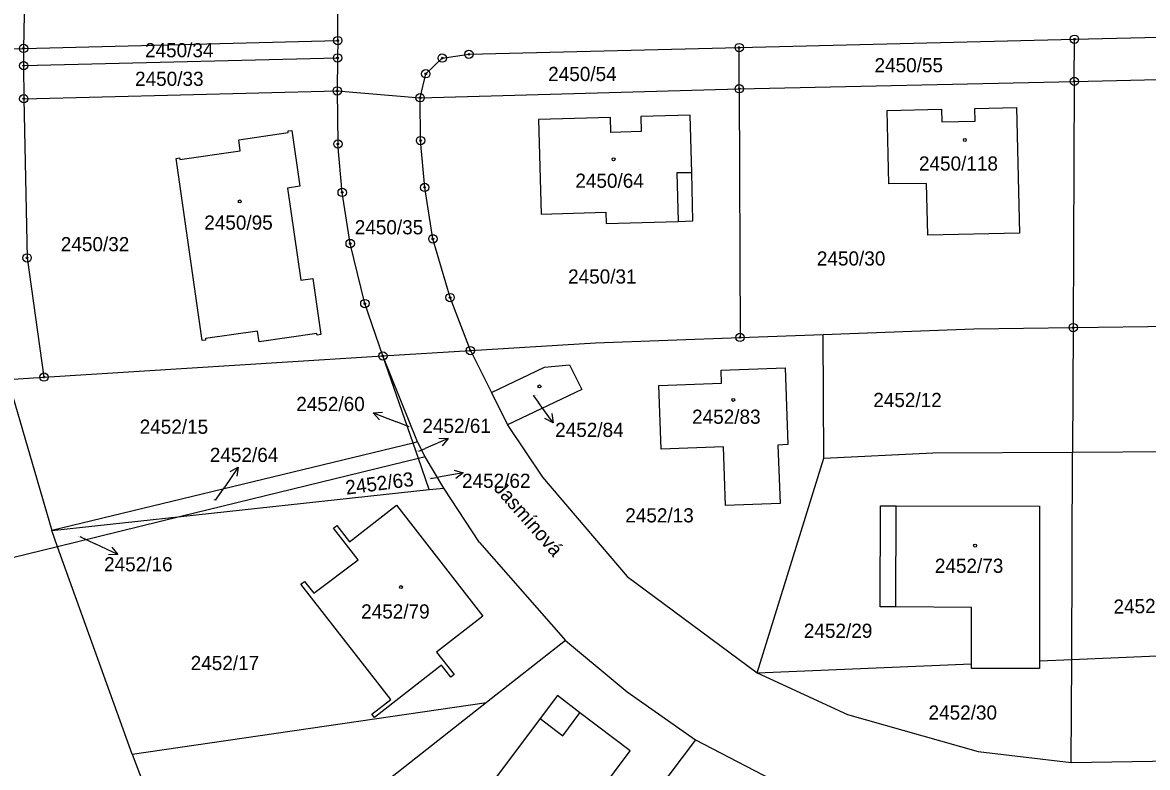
# Model space of a CAD drawing. Extents: x -755819 to -753140, y -1169796 to -1166000.
# Drawn here: x -755181.4 to -755046.4, y -1168484.4 to -1168395 of the extents above; entities that cross this region are included whole.
import ezdxf

# ---------------------------------------------------------------- set-up
doc = ezdxf.new("R2010")
doc.units = 0
for name, color, linetype in [('Vrstva 1', 7, 'Continuous'), ('Vrstva 15', 7, 'Continuous'), ('Vrstva 16', 7, 'Continuous'), ('Vrstva 18', 7, 'Continuous'), ('Vrstva 19', 7, 'Continuous'), ('Vrstva 24', 7, 'Continuous'), ('Vrstva 25', 7, 'Continuous'), ('Vrstva 4', 7, 'Continuous'), ('Vrstva 6', 7, 'Continuous')]:
    doc.layers.add(name, color=color, linetype=linetype)

msp = doc.modelspace()

# ---------------------------------------------------------------- linework, layer by layer
at = {"layer": 'Vrstva 1'}
for p, q in [((-755180.52, -1168361.47), (-755181.23, -1168398.1)), ((-755143.53, -1168397.15), (-755143.58, -1168361.49)), ((-755055.13, -1168396.99), (-755015.3, -1168396)), ((-755192.3, -1168398.38), (-755181.23, -1168398.1)), ((-755181.23, -1168398.1), (-755143.53, -1168397.15)), ((-755181.23, -1168398.1), (-755181.22, -1168400.16)), ((-755143.53, -1168397.15), (-755143.55, -1168399.23)), ((-755127.79, -1168398.8), (-755095.36, -1168397.99)), ((-755095.36, -1168397.99), (-755055.13, -1168396.99)), ((-755095.35, -1168402.94), (-755095.36, -1168397.99)), ((-755055.15, -1168402.05), (-755055.13, -1168396.99)), ((-755181.22, -1168400.16), (-755143.55, -1168399.23)), ((-755143.55, -1168399.23), (-755143.59, -1168403.19)), ((-755132.97, -1168401.14), (-755130.99, -1168399.26)), ((-755130.99, -1168399.26), (-755127.79, -1168398.8)), ((-755181.22, -1168400.16), (-755181.2, -1168404.13)), ((-755133.65, -1168404.02), (-755132.97, -1168401.14)), ((-755095.35, -1168402.94), (-755055.15, -1168402.05)), ((-755055.15, -1168402.05), (-755055.28, -1168431.59)), ((-755055.15, -1168402.05), (-755015.29, -1168401.09)), ((-755181.2, -1168404.13), (-755143.59, -1168403.19)), ((-755143.59, -1168403.19), (-755143.51, -1168409.56)), ((-755143.59, -1168403.19), (-755133.65, -1168404.02)), ((-755133.65, -1168404.02), (-755095.35, -1168402.94)), ((-755095.35, -1168402.94), (-755095.26, -1168432.77)), ((-755181.2, -1168404.13), (-755180.81, -1168423.22)), ((-755133.59, -1168409.15), (-755133.65, -1168404.02)), ((-755110.81, -1168406.39), (-755119.46, -1168406.62)), ((-755110.77, -1168408.19), (-755110.81, -1168406.39)), ((-755101.24, -1168406.12), (-755107.17, -1168406.28)), ((-755107.17, -1168406.28), (-755107.13, -1168408.06)), ((-755101.04, -1168413.02), (-755101.24, -1168406.12)), ((-755077.61, -1168405.55), (-755071.07, -1168405.4)), ((-755077.42, -1168414.34), (-755077.61, -1168405.55)), ((-755071.07, -1168405.4), (-755071.03, -1168406.9)), ((-755067.07, -1168405.31), (-755062.08, -1168405.2)), ((-755067.04, -1168406.81), (-755067.07, -1168405.31)), ((-755062.08, -1168405.2), (-755061.74, -1168420.24)), ((-755119.46, -1168406.62), (-755119.13, -1168417.97)), ((-755071.03, -1168406.9), (-755067.04, -1168406.81)), ((-755155.41, -1168409.07), (-755149.46, -1168408.18)), ((-755155.25, -1168410.38), (-755155.41, -1168409.07)), ((-755149.47, -1168407.99), (-755149.03, -1168407.96)), ((-755149.46, -1168408.18), (-755149.47, -1168407.99)), ((-755149.03, -1168407.96), (-755148.1, -1168414.63)), ((-755107.13, -1168408.06), (-755110.77, -1168408.19)), ((-755162.47, -1168411.44), (-755155.25, -1168410.38)), ((-755143, -1168415.37), (-755143.51, -1168409.56)), ((-755133.1, -1168414.78), (-755133.59, -1168409.15)), ((-755162.93, -1168411.29), (-755162.5, -1168411.24)), ((-755159.81, -1168433.15), (-755162.93, -1168411.29)), ((-755162.5, -1168411.24), (-755162.47, -1168411.44)), ((-755100.93, -1168418.78), (-755101.04, -1168413.02)), ((-755072.87, -1168414.29), (-755077.42, -1168414.34)), ((-755072.73, -1168420.48), (-755072.87, -1168414.29)), ((-755148.1, -1168414.63), (-755149.55, -1168414.85)), ((-755149.55, -1168414.85), (-755147.97, -1168425.9)), ((-755142.04, -1168421.5), (-755143, -1168415.37)), ((-755132.12, -1168420.94), (-755133.1, -1168414.78)), ((-755119.13, -1168417.97), (-755111.35, -1168417.74)), ((-755111.35, -1168417.74), (-755111.34, -1168419.09)), ((-755111.34, -1168419.09), (-755102.69, -1168418.85)), ((-755102.69, -1168418.85), (-755100.93, -1168418.78)), ((-755130.05, -1168427.99), (-755132.12, -1168420.94)), ((-755061.74, -1168420.24), (-755072.73, -1168420.48)), ((-755140.28, -1168428.71), (-755142.04, -1168421.5)), ((-755180.81, -1168423.22), (-755178.78, -1168437.53)), ((-755147.97, -1168425.9), (-755146.52, -1168425.71)), ((-755146.52, -1168425.71), (-755145.56, -1168432.42)), ((-755127.62, -1168434.34), (-755130.05, -1168427.99)), ((-755138.11, -1168434.99), (-755140.28, -1168428.71)), ((-755153.14, -1168432), (-755159.41, -1168432.88)), ((-755152.95, -1168433.29), (-755153.14, -1168432)), ((-755085.27, -1168432.41), (-755067.2, -1168431.75)), ((-755067.2, -1168431.75), (-755055.28, -1168431.59)), ((-755055.28, -1168431.59), (-755055.35, -1168446.53)), ((-755055.28, -1168431.59), (-755015.24, -1168431.05)), ((-755159.38, -1168433.08), (-755159.81, -1168433.15)), ((-755159.41, -1168432.88), (-755159.38, -1168433.08)), ((-755146.03, -1168432.29), (-755152.95, -1168433.29)), ((-755146, -1168432.48), (-755146.03, -1168432.29)), ((-755145.56, -1168432.42), (-755146, -1168432.48)), ((-755127.62, -1168434.34), (-755112.6, -1168433.4)), ((-755112.6, -1168433.4), (-755095.26, -1168432.77)), ((-755095.26, -1168432.77), (-755085.27, -1168432.41)), ((-755085.21, -1168447.26), (-755085.27, -1168432.41)), ((-755138.11, -1168434.99), (-755127.62, -1168434.34)), ((-755127.62, -1168434.34), (-755125.1, -1168439.38)), ((-755178.78, -1168437.53), (-755138.11, -1168434.99)), ((-755134.5, -1168445.44), (-755138.11, -1168434.99)), ((-755133.95, -1168445.3), (-755138.11, -1168434.99)), ((-755118.73, -1168436.35), (-755115.74, -1168436.05)), ((-755115.74, -1168436.05), (-755114.25, -1168439.03)), ((-755125.1, -1168439.38), (-755118.73, -1168436.35)), ((-755097.54, -1168436.7), (-755089.86, -1168436.41)), ((-755097.49, -1168438.26), (-755097.54, -1168436.7)), ((-755089.86, -1168436.41), (-755089.52, -1168445.62)), ((-755183.1, -1168437.8), (-755178.78, -1168437.53)), ((-755105.01, -1168438.52), (-755097.49, -1168438.26)), ((-755104.74, -1168446.18), (-755105.01, -1168438.52)), ((-755125.1, -1168439.38), (-755123.16, -1168443.26)), ((-755114.25, -1168439.03), (-755123.16, -1168443.26)), ((-755123.16, -1168443.26), (-755123.06, -1168443.45)), ((-755123.06, -1168443.45), (-755118.96, -1168449.54)), ((-755134.5, -1168445.44), (-755177.85, -1168455.95)), ((-755133.95, -1168445.3), (-755134.5, -1168445.44)), ((-755133.86, -1168447.3), (-755134.5, -1168445.44)), ((-755133.05, -1168447.1), (-755133.95, -1168445.3)), ((-755097.26, -1168445.89), (-755104.74, -1168446.18)), ((-755097.01, -1168452.92), (-755097.26, -1168445.89)), ((-755089.52, -1168445.62), (-755090.73, -1168445.7)), ((-755090.73, -1168445.7), (-755090.46, -1168452.71)), ((-755085.21, -1168447.26), (-755072.12, -1168446.63)), ((-755072.12, -1168446.63), (-755055.35, -1168446.53)), ((-755055.46, -1168471.41), (-755055.35, -1168446.53)), ((-755055.35, -1168446.53), (-755015.21, -1168446.3)), ((-755133.86, -1168447.3), (-755162.35, -1168454.27)), ((-755133.05, -1168447.1), (-755133.86, -1168447.3)), ((-755132.57, -1168451.03), (-755133.86, -1168447.3)), ((-755130.81, -1168450.84), (-755133.05, -1168447.1)), ((-755093.19, -1168472.99), (-755085.21, -1168447.26)), ((-755118.96, -1168449.54), (-755108.82, -1168461.44)), ((-755132.57, -1168451.03), (-755130.81, -1168450.84)), ((-755126.54, -1168457.36), (-755130.81, -1168450.84)), ((-755162.35, -1168454.27), (-755132.57, -1168451.03)), ((-755142.13, -1168457.28), (-755136.47, -1168452.9)), ((-755136.47, -1168452.9), (-755126.11, -1168466.19)), ((-755090.46, -1168452.71), (-755097.01, -1168452.92)), ((-755078.45, -1168465.09), (-755078.42, -1168452.96)), ((-755078.42, -1168452.96), (-755076.54, -1168452.97)), ((-755076.54, -1168452.97), (-755059.34, -1168453)), ((-755059.34, -1168453), (-755059.34, -1168471.57)), ((-755177.85, -1168455.95), (-755162.35, -1168454.27)), ((-755162.35, -1168454.27), (-755177.15, -1168457.89)), ((-755144.05, -1168455.65), (-755143.64, -1168455.35)), ((-755141.09, -1168459.43), (-755144.05, -1168455.65)), ((-755143.64, -1168455.35), (-755142.13, -1168457.28)), ((-755126.54, -1168457.36), (-755116.19, -1168469.11)), ((-755177.15, -1168457.89), (-755188.54, -1168460.68)), ((-755146.39, -1168463.44), (-755141.09, -1168459.43)), ((-755108.82, -1168461.44), (-755093.19, -1168472.99)), ((-755147.95, -1168462.35), (-755147.54, -1168462.05)), ((-755137.15, -1168476.19), (-755147.95, -1168462.35)), ((-755147.54, -1168462.05), (-755146.39, -1168463.44)), ((-755076.57, -1168465.1), (-755078.45, -1168465.09)), ((-755067.47, -1168465.15), (-755076.57, -1168465.1)), ((-755067.49, -1168471.91), (-755067.47, -1168465.15)), ((-755126.11, -1168466.19), (-755131.67, -1168470.51)), ((-755116.19, -1168469.11), (-755125.69, -1168476.58)), ((-755116.19, -1168469.11), (-755110.02, -1168474.29)), ((-755131.67, -1168470.51), (-755129.57, -1168473.21)), ((-755131.07, -1168472.09), (-755139.12, -1168478.36)), ((-755129.96, -1168473.52), (-755131.07, -1168472.09)), ((-755067.49, -1168472.47), (-755067.49, -1168471.91)), ((-755059.34, -1168472.49), (-755067.49, -1168472.47)), ((-755059.34, -1168471.57), (-755059.34, -1168472.49)), ((-755055.51, -1168483.78), (-755055.46, -1168471.41)), ((-755129.57, -1168473.21), (-755129.96, -1168473.52)), ((-755093.19, -1168472.99), (-755082.38, -1168478.02)), ((-755110.02, -1168474.29), (-755108.82, -1168475.29)), ((-755125.69, -1168476.58), (-755160.25, -1168503.73)), ((-755139.43, -1168477.97), (-755137.15, -1168476.19)), ((-755117.18, -1168475.73), (-755119.26, -1168478.5)), ((-755114.48, -1168477.8), (-755117.18, -1168475.73)), ((-755108.82, -1168475.29), (-755100.62, -1168481.04)), ((-755108.43, -1168482.37), (-755114.48, -1168477.8)), ((-755139.12, -1168478.36), (-755139.43, -1168477.97)), ((-755119.26, -1168478.5), (-755128.05, -1168490.22)), ((-755082.38, -1168478.02), (-755066.7, -1168482.46)), ((-755100.62, -1168481.04), (-755113.58, -1168498.25)), ((-755100.62, -1168481.04), (-755088.52, -1168487.31)), ((-755119.3, -1168496.79), (-755108.43, -1168482.37)), ((-755066.7, -1168482.46), (-755055.51, -1168483.78)), ((-755055.51, -1168483.78), (-755015.37, -1168483.03))]:
    msp.add_line(p, q, dxfattribs=at)
at = {"layer": 'Vrstva 16'}
for p, q in [((-755120.07, -1168439.72), (-755119.44, -1168440.58)), ((-755117.68, -1168443.01), (-755119.44, -1168440.58)), ((-755139.28, -1168441.83), (-755136.48, -1168442.9)), ((-755134.95, -1168443.48), (-755136.48, -1168442.9)), ((-755130.29, -1168444.9), (-755133.04, -1168446.09)), ((-755133.79, -1168446.42), (-755133.04, -1168446.09)), ((-755155.46, -1168448.33), (-755157.16, -1168450.8)), ((-755132.41, -1168449.71), (-755131.43, -1168449.54)), ((-755128.48, -1168449.02), (-755131.43, -1168449.54)), ((-755158.2, -1168452.31), (-755157.16, -1168450.8)), ((-755174.49, -1168456.64), (-755172.64, -1168457.52)), ((-755169.93, -1168458.81), (-755172.64, -1168457.52))]:
    msp.add_line(p, q, dxfattribs=at)
for points in [[(-755138.53, -1168442.65), (-755139.28, -1168441.83), (-755138.17, -1168441.72)], [(-755117.86, -1168441.91), (-755117.68, -1168443.01), (-755118.67, -1168442.49)], [(-755131.4, -1168444.84), (-755130.29, -1168444.9), (-755131.01, -1168445.76)], [(-755156.44, -1168448.87), (-755155.46, -1168448.33), (-755155.62, -1168449.43)], [(-755129.55, -1168448.7), (-755128.48, -1168449.02), (-755129.37, -1168449.68)], [(-755170.62, -1168457.93), (-755169.93, -1168458.81), (-755171.05, -1168458.83)]]:
    msp.add_lwpolyline(points, dxfattribs=at)
at = {"layer": 'Vrstva 24'}
for centre, radius in [((-755143.53, -1168397.15), 0.5), ((-755055.13, -1168396.99), 0.5), ((-755055.13, -1168396.99), 0.1), ((-755181.23, -1168398.1), 0.5), ((-755181.23, -1168398.1), 0.1), ((-755143.53, -1168397.15), 0.1), ((-755127.79, -1168398.8), 0.5), ((-755095.36, -1168397.99), 0.5), ((-755095.36, -1168397.99), 0.1), ((-755181.22, -1168400.16), 0.5), ((-755143.55, -1168399.23), 0.5), ((-755143.55, -1168399.23), 0.1), ((-755130.99, -1168399.26), 0.5), ((-755130.99, -1168399.26), 0.1), ((-755127.79, -1168398.8), 0.1), ((-755181.22, -1168400.16), 0.1), ((-755132.97, -1168401.14), 0.5), ((-755132.97, -1168401.14), 0.1), ((-755055.15, -1168402.05), 0.5), ((-755055.15, -1168402.05), 0.1), ((-755181.2, -1168404.13), 0.5), ((-755143.59, -1168403.19), 0.5), ((-755143.59, -1168403.19), 0.1), ((-755133.65, -1168404.02), 0.5), ((-755095.35, -1168402.94), 0.5), ((-755095.35, -1168402.94), 0.1), ((-755181.2, -1168404.13), 0.1), ((-755133.65, -1168404.02), 0.1), ((-755143.51, -1168409.56), 0.5), ((-755133.59, -1168409.15), 0.5), ((-755133.59, -1168409.15), 0.1), ((-755143.51, -1168409.56), 0.1), ((-755133.1, -1168414.78), 0.5), ((-755143, -1168415.37), 0.5), ((-755143, -1168415.37), 0.1), ((-755133.1, -1168414.78), 0.1), ((-755142.04, -1168421.5), 0.5), ((-755132.12, -1168420.94), 0.5), ((-755132.12, -1168420.94), 0.1), ((-755142.04, -1168421.5), 0.1), ((-755180.81, -1168423.22), 0.5), ((-755180.81, -1168423.22), 0.1), ((-755130.05, -1168427.99), 0.5), ((-755130.05, -1168427.99), 0.1), ((-755140.28, -1168428.71), 0.5), ((-755140.28, -1168428.71), 0.1), ((-755055.28, -1168431.59), 0.5), ((-755055.28, -1168431.59), 0.1), ((-755095.26, -1168432.77), 0.5), ((-755095.26, -1168432.77), 0.1), ((-755138.11, -1168434.99), 0.5), ((-755127.62, -1168434.34), 0.5), ((-755127.62, -1168434.34), 0.1), ((-755138.11, -1168434.99), 0.1), ((-755178.78, -1168437.53), 0.5), ((-755178.78, -1168437.53), 0.1)]:
    msp.add_circle(centre, radius, dxfattribs=at)
at = {"layer": 'Vrstva 25'}
for centre in [(-755068.28, -1168409.08), (-755110.43, -1168411.4), (-755155.29, -1168416.45), (-755119.33, -1168438.65), (-755096.07, -1168440.27), (-755067.06, -1168457.75), (-755135.95, -1168462.72)]:
    msp.add_circle(centre, 0.175, dxfattribs=at)
at = {"layer": 'Vrstva 4'}
for p, q in [((-755101.04, -1168413.02), (-755102.84, -1168413.04)), ((-755102.84, -1168413.04), (-755102.69, -1168418.85)), ((-755076.57, -1168465.1), (-755076.54, -1168452.97)), ((-755116.54, -1168480.56), (-755114.48, -1168477.8)), ((-755119.26, -1168478.5), (-755116.54, -1168480.56))]:
    msp.add_line(p, q, dxfattribs=at)
at = {"layer": 'Vrstva 6'}
for p, q in [((-755183.1, -1168437.8), (-755177.85, -1168455.95)), ((-755177.15, -1168457.89), (-755177.85, -1168455.95)), ((-755168.2, -1168482.78), (-755177.15, -1168457.89)), ((-755055.46, -1168471.41), (-755015.31, -1168469.74)), ((-755093.19, -1168472.99), (-755067.49, -1168471.91)), ((-755059.34, -1168471.57), (-755055.46, -1168471.41)), ((-755168.2, -1168482.78), (-755125.69, -1168476.58)), ((-755168.2, -1168482.78), (-755160.25, -1168503.73))]:
    msp.add_line(p, q, dxfattribs=at)

# ---------------------------------------------------------------- texts
at = {"layer": 'Vrstva 15'}
msp.add_text('Jasmínová', height=1.7, rotation=311.2307, dxfattribs=at).set_placement((-755124.89, -1168450.94))
at = {"layer": 'Vrstva 16'}
for s, p in [('2452/60', (-755148.51, -1168441.6)), ('2452/61', (-755133.37, -1168444.22)), ('2452/84', (-755117.44, -1168444.71)), ('2452/64', (-755158.88, -1168447.71)), ('2452/62', (-755128.62, -1168450.82)), ('2452/16', (-755171.57, -1168460.83))]:
    msp.add_text(s, height=1.7, dxfattribs=at).set_placement(p)
at = {"layer": 'Vrstva 18'}
for s, height, p in [('2450/34', 1.7, (-755166.66, -1168399.16)), ('2450/55', 1.7, (-755079.12, -1168400.96)), ('2450/33', 1.7, (-755167.85, -1168402.59)), ('2450/54', 1.7, (-755118.28, -1168402.01)), ('2450/35', 1.7, (-755141.49, -1168420.4)), ('2450/32', 1.7, (-755176.76, -1168422.43)), ('2450/30', 1.7, (-755086.04, -1168424.14)), ('2450/31', 1.7, (-755115.89, -1168426.31)), ('2452/12', 1.7, (-755079.27, -1168441.12)), ('2452/15', 1.7, (-755167.3, -1168444.33)), ('2452/60', 0.1, (-755135.25, -1168443.48)), ('2452/61', 0.1, (-755134.06, -1168446.42)), ('2452/62', 0.1, (-755132.71, -1168449.71)), ('2452/64', 0.1, (-755158.49, -1168452.31)), ('2452/13', 1.7, (-755109.03, -1168454.96)), ('2452/16', 0.1, (-755174.76, -1168456.64)), ('2452/29', 1.7, (-755087.6, -1168468.81)), ('2452/17', 1.7, (-755161.18, -1168472.68)), ('2452/30', 1.7, (-755072.64, -1168478.62))]:
    msp.add_text(s, height=height, dxfattribs=at).set_placement(p)
for s, rotation, p in [('2452/63', 7.4485, (-755142.49, -1168451.64)), ('2452/31', 1.0886, (-755050.43, -1168465.92))]:
    msp.add_text(s, height=1.7, rotation=rotation, dxfattribs=at).set_placement(p)
at = {"layer": 'Vrstva 19'}
for s, height, p in [('2450/118', 1.7, (-755073.79, -1168412.75)), ('2450/64', 1.7, (-755115.02, -1168414.82)), ('2450/95', 1.7, (-755159.55, -1168419.84)), ('2452/84', 0.1, (-755120.06, -1168439.72)), ('2452/83', 1.7, (-755101.01, -1168443.13)), ('2452/73', 1.7, (-755071.88, -1168461.01)), ('2452/79', 1.7, (-755140.72, -1168466.49))]:
    msp.add_text(s, height=height, dxfattribs=at).set_placement(p)

doc.saveas('drawing.dxf')
